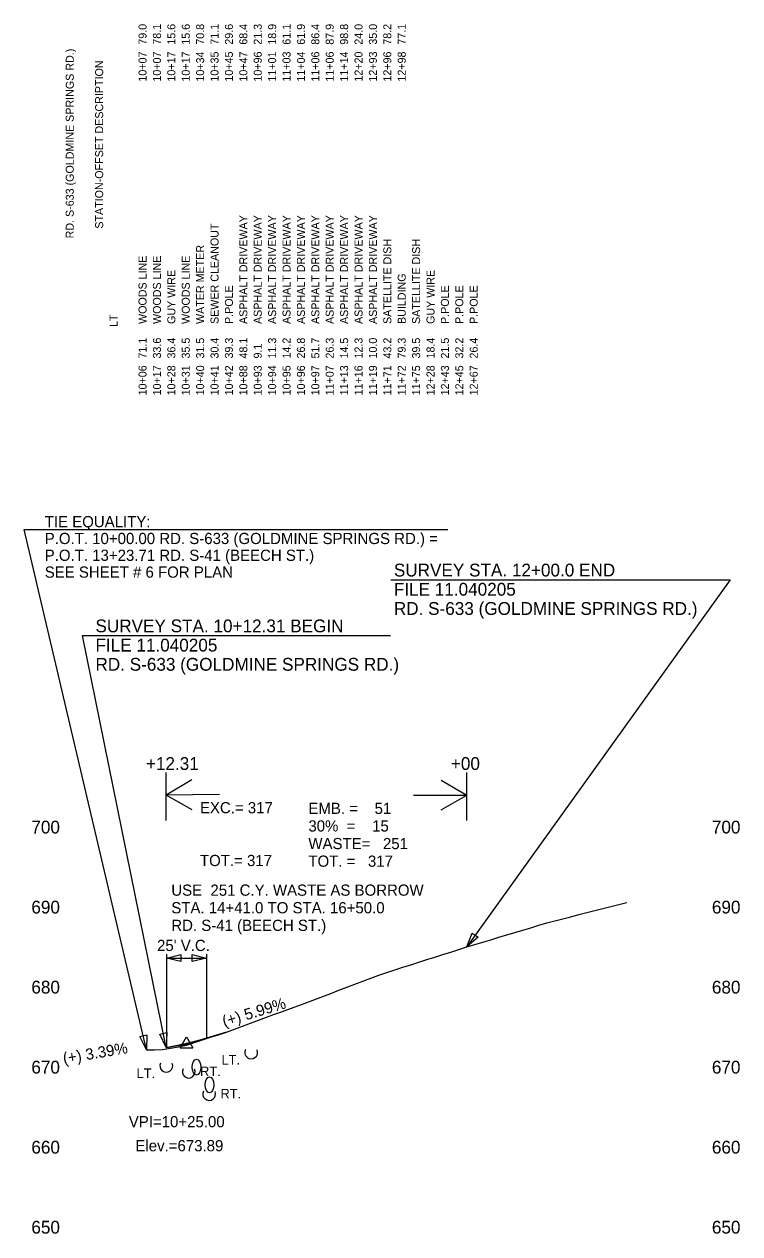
# Model space of a CAD drawing. Extents: x 16382402 to 16388022, y 46194326 to 46202918.
# Drawn here: x 16384675 to 16385122, y 46196922 to 46197677 of the extents above; entities that cross this region are included whole.
import ezdxf

# ---------------------------------------------------------------- set-up
doc = ezdxf.new("R2010")
doc.units = 0
for name, color, linetype in [('Default', 7, 'Continuous'), ('RD_DDB_ElevTX', 7, 'Continuous'), ('RD_DDB_GradeTX', 7, 'Continuous'), ('RD_DDB_Profile_EX', 7, 'Continuous'), ('RD_DDB_Profile_Lbl', 7, 'Continuous'), ('RD_DDB_Profile_PR', 7, 'Continuous'), ('RD_DDB_VCLbl', 7, 'Continuous'), ('RD_HC_Data', 7, 'Continuous'), ('RD_PD_Final_TX', 7, 'Continuous'), ('RD_TX_Bldg', 7, 'Continuous'), ('RD_TX_Drainage', 7, 'Continuous')]:
    doc.layers.add(name, color=color, linetype=linetype)

msp = doc.modelspace()

# ---------------------------------------------------------------- linework, layer by layer
at = {"layer": 'Default'}
for p, q in [((16384763.66, 46197179.88), (16384763.66, 46197209.88)), ((16384951.35, 46197179.88), (16384951.35, 46197209.88)), ((16384779.68, 46197205.24), (16384763.66, 46197195.8)), ((16384935.25, 46197205.1), (16384951.35, 46197195.8)), ((16384796.99, 46197196.09), (16384763.66, 46197195.8)), ((16384779.84, 46197186.64), (16384763.66, 46197195.8)), ((16384918.02, 46197195.8), (16384951.35, 46197195.8)), ((16384935.25, 46197186.5), (16384951.35, 46197195.8))]:
    msp.add_line(p, q, dxfattribs=at)
for centre in [(16384816.72, 46197035.01), (16384763.69, 46197026.63), (16384777.69, 46197022.98), (16384790.44, 46197009.03)]:
    msp.add_arc(centre, 3.98, 153.82804, 22.53319, dxfattribs=at)
at = {"layer": 'RD_DDB_GradeTX'}
for p in [(16384801.35, 46197047.74), (16384763.66, 46197038.1)]:
    msp.add_line(p, (16384776.35, 46197040.25), dxfattribs=at)
at = {"layer": 'RD_DDB_Profile_EX'}
msp.add_lwpolyline([(16384751.35, 46197036.69), (16384756.35, 46197036.73), (16384761.35, 46197036.83), (16384766.35, 46197037.65), (16384771.35, 46197038.48), (16384776.35, 46197039.54), (16384781.35, 46197041.17), (16384786.35, 46197042.81), (16384791.35, 46197044.45), (16384796.35, 46197046.09), (16384801.35, 46197047.74), (16384806.35, 46197049.59), (16384811.35, 46197051.44), (16384816.35, 46197053.29), (16384821.35, 46197055.14), (16384826.35, 46197056.99), (16384831.35, 46197058.84), (16384836.35, 46197060.69), (16384841.35, 46197062.52), (16384846.35, 46197064.36), (16384851.35, 46197066.21), (16384856.35, 46197068.1), (16384861.35, 46197070.02), (16384866.35, 46197071.93), (16384871.35, 46197073.83), (16384876.35, 46197075.71), (16384881.35, 46197077.59), (16384886.35, 46197079.47), (16384891.35, 46197081.35), (16384896.35, 46197083.23), (16384901.35, 46197085.04), (16384906.35, 46197086.62), (16384911.35, 46197088.2), (16384916.35, 46197089.79), (16384921.35, 46197091.37), (16384926.35, 46197092.99), (16384931.35, 46197094.57), (16384936.35, 46197096.16), (16384941.35, 46197097.74), (16384946.35, 46197099.32), (16384951.35, 46197100.94), (16384956.35, 46197102.45), (16384961.35, 46197103.95), (16384966.35, 46197105.45), (16384971.35, 46197106.94), (16384976.35, 46197108.44), (16384981.35, 46197109.94), (16384986.35, 46197111.43), (16384991.35, 46197112.93), (16384996.35, 46197114.43), (16385001.35, 46197115.93), (16385006.35, 46197117.31), (16385011.35, 46197118.57), (16385016.35, 46197119.83), (16385021.35, 46197121.09), (16385026.35, 46197122.34), (16385031.35, 46197123.6), (16385036.35, 46197124.85), (16385041.35, 46197126.11), (16385046.35, 46197127.36), (16385051.35, 46197128.62)], dxfattribs=at)
at = {"layer": 'RD_DDB_Profile_PR'}
for p, q in [((16384788.85, 46197044), (16384801.35, 46197047.74)), ((16384763.66, 46197038.1), (16384763.85, 46197038.13))]:
    msp.add_line(p, q, dxfattribs=at)
msp.add_spline([(16384763.85, 46197038.13), (16384764.35, 46197038.22), (16384764.85, 46197038.3), (16384765.35, 46197038.39), (16384765.85, 46197038.48), (16384766.35, 46197038.57), (16384766.85, 46197038.66), (16384767.35, 46197038.76), (16384767.85, 46197038.85), (16384768.35, 46197038.95), (16384768.85, 46197039.05), (16384769.35, 46197039.14), (16384769.85, 46197039.24), (16384770.35, 46197039.34), (16384770.85, 46197039.45), (16384771.35, 46197039.55), (16384771.85, 46197039.66), (16384772.35, 46197039.76), (16384772.85, 46197039.87), (16384773.35, 46197039.98), (16384773.85, 46197040.09), (16384774.35, 46197040.2), (16384774.85, 46197040.31), (16384775.35, 46197040.43), (16384775.85, 46197040.54), (16384776.35, 46197040.66), (16384776.85, 46197040.78), (16384777.35, 46197040.9), (16384777.85, 46197041.02), (16384778.35, 46197041.14), (16384778.85, 46197041.26), (16384779.35, 46197041.39), (16384779.85, 46197041.51), (16384780.35, 46197041.64), (16384780.85, 46197041.77), (16384781.35, 46197041.9), (16384781.85, 46197042.03), (16384782.35, 46197042.16), (16384782.85, 46197042.29), (16384783.35, 46197042.43), (16384783.85, 46197042.56), (16384784.35, 46197042.7), (16384784.85, 46197042.84), (16384785.35, 46197042.98), (16384785.85, 46197043.12), (16384786.35, 46197043.27), (16384786.85, 46197043.41), (16384787.35, 46197043.55), (16384787.85, 46197043.7), (16384788.35, 46197043.85), (16384788.85, 46197044)], degree=3, dxfattribs=at)
at = {"layer": 'RD_DDB_VCLbl'}
for p, q in [((16384763.85, 46197096.5), (16384763.85, 46197038.13)), ((16384763.85, 46197094), (16384788.85, 46197094)), ((16384788.85, 46197096.5), (16384788.85, 46197044))]:
    msp.add_line(p, q, dxfattribs=at)
at = {"layer": 'RD_HC_Data'}
for p, q in [((16384674.94, 46197361.72), (16384939.6, 46197361.72)), ((16384751.35, 46197036.69), (16384674.94, 46197361.72)), ((16384772.38, 46197037.96), (16384776.35, 46197044.84)), ((16384776.35, 46197044.84), (16384780.32, 46197037.96)), ((16384772.38, 46197037.96), (16384780.32, 46197037.96))]:
    msp.add_line(p, q, dxfattribs=at)
msp.add_circle((16384776.35, 46197040.25), 0.529, dxfattribs=at)
at = {"layer": 'RD_PD_Final_TX'}
for p, q in [((16384904, 46197330.38), (16385115.78, 46197330.38)), ((16385115.78, 46197330.38), (16384951.35, 46197100.94)), ((16384711.44, 46197295.49), (16384903.65, 46197295.49)), ((16384763.66, 46197038.1), (16384711.44, 46197295.49))]:
    msp.add_line(p, q, dxfattribs=at)
at = {"layer": 'RD_TX_Drainage'}
for points in [[(16384958.42, 46197106.95), (16384951.35, 46197100.94), (16384954.76, 46197109.57)], [(16384772.85, 46197091.75), (16384763.85, 46197094), (16384772.85, 46197096.25)], [(16384779.85, 46197096.25), (16384788.85, 46197094), (16384779.85, 46197091.75)], [(16384764.08, 46197047.37), (16384763.66, 46197038.1), (16384759.67, 46197046.47)], [(16384751.48, 46197045.97), (16384751.35, 46197036.69), (16384747.1, 46197044.94)]]:
    msp.add_lwpolyline(points, close=True, dxfattribs=at)
for centre in [(16384782.53, 46197025.8), (16384790.66, 46197014.8)]:
    msp.add_ellipse(centre, major_axis=(0, 5), ratio=0.529493, dxfattribs=at)

# ---------------------------------------------------------------- texts
at = {"layer": 'Default'}
for s, height, p in [('+12.31', 8, (16384750.95, 46197211.51)), ('+00', 8, (16384941.4, 46197211.51)), ('EXC.= 317', 7, (16384784.7, 46197184.44)), ('EMB. =    51', 7, (16384852.42, 46197184.02)), ('30%  =    15', 7, (16384852.42, 46197173.02)), ('WASTE=   251', 7, (16384852.42, 46197162.02)), ('TOT.= 317', 7, (16384784.7, 46197151.44)), ('TOT. =   317', 7, (16384852.42, 46197151.02)), ('USE  251 C.Y. WASTE AS BORROW', 7, (16384766.81, 46197132.92)), ('STA. 14+41.0 TO STA. 16+50.0', 7, (16384766.81, 46197121.92)), ('RD. S-41 (BEECH ST.)', 7, (16384766.81, 46197110.92)), ('LT.', 6, (16384798.13, 46197027.39)), ('LT.', 6, (16384745.1, 46197019.01)), ('RT.', 6, (16384784.77, 46197020.2)), ('RT.', 6, (16384797.52, 46197006.25))]:
    msp.add_text(s, height=height, dxfattribs=at).set_placement(p)
at = {"layer": 'RD_DDB_ElevTX'}
for s, p in [('700', (16384679.41, 46197171.8)), ('700', (16385104.41, 46197171.8)), ('690', (16384679.41, 46197121.8)), ('690', (16385104.41, 46197121.8)), ('680', (16384679.41, 46197071.8)), ('680', (16385104.41, 46197071.8)), ('670', (16384679.41, 46197021.8)), ('670', (16385104.41, 46197021.8)), ('660', (16384679.41, 46196971.8)), ('660', (16385104.41, 46196971.8)), ('650', (16384679.41, 46196921.8)), ('650', (16385104.41, 46196921.8))]:
    msp.add_text(s, height=8, dxfattribs=at).set_placement(p)
at = {"layer": 'RD_DDB_GradeTX'}
for s, rotation, p in [('(+) 5.99%', 16.81672, (16384799.86, 46197050.93)), ('(+) 3.39%', 9.62593, (16384699.74, 46197027.8))]:
    msp.add_text(s, height=7, rotation=rotation, dxfattribs=at).set_placement(p)
at = {"layer": 'RD_DDB_Profile_Lbl'}
for s, p in [('VPI=10+25.00', (16384740.26, 46196988.25)), ('Elev.=673.89', (16384744.4, 46196973.25))]:
    msp.add_text(s, height=7, dxfattribs=at).set_placement(p)
at = {"layer": 'RD_DDB_VCLbl'}
msp.add_text("25' V.C.", height=7, dxfattribs=at).set_placement((16384757.91, 46197098.37))
at = {"layer": 'RD_HC_Data'}
for s, p in [('TIE EQUALITY:', (16384687.76, 46197363.14)), ('P.O.T. 10+00.00 RD. S-633 (GOLDMINE SPRINGS RD.) =', (16384687.76, 46197352.64)), ('P.O.T. 13+23.71 RD. S-41 (BEECH ST.)', (16384687.76, 46197342.14)), ('SEE SHEET # 6 FOR PLAN', (16384687.76, 46197331.64))]:
    msp.add_text(s, height=7, dxfattribs=at).set_placement(p)
at = {"layer": 'RD_PD_Final_TX'}
for s, p in [('SURVEY STA. 12+00.0 END', (16384905.8, 46197332.39)), ('FILE 11.040205', (16384905.8, 46197320.39)), ('RD. S-633 (GOLDMINE SPRINGS RD.)', (16384905.8, 46197308.39)), ('SURVEY STA. 10+12.31 BEGIN', (16384719.44, 46197297.51)), ('FILE 11.040205', (16384719.44, 46197285.51)), ('RD. S-633 (GOLDMINE SPRINGS RD.)', (16384719.44, 46197273.51))]:
    msp.add_text(s, height=8, dxfattribs=at).set_placement(p)
at = {"layer": 'RD_TX_Bldg'}
for s, p in [('79.0', (16384751.35, 46197664.65)), ('78.1', (16384760.34, 46197664.65)), ('15.6', (16384769.33, 46197664.65)), ('15.6', (16384778.33, 46197664.65)), ('70.8', (16384787.32, 46197664.65)), ('71.1', (16384796.31, 46197664.65)), ('29.6', (16384805.3, 46197664.65)), ('68.4', (16384814.29, 46197664.65)), ('21.3', (16384823.28, 46197664.65)), ('18.9', (16384832.28, 46197664.65)), ('61.1', (16384841.27, 46197664.65)), ('61.9', (16384850.26, 46197664.65)), ('86.4', (16384859.25, 46197664.65)), ('87.9', (16384868.24, 46197664.65)), ('98.8', (16384877.23, 46197664.65)), ('24.0', (16384886.23, 46197664.65)), ('35.0', (16384895.22, 46197664.65)), ('78.2', (16384904.21, 46197664.65)), ('77.1', (16384913.2, 46197664.65)), ('RD. S-633 (GOLDMINE SPRINGS RD.)', (16384705.89, 46197543.64)), ('10+07', (16384751.35, 46197641.6)), ('10+07', (16384760.34, 46197641.6)), ('10+17', (16384769.33, 46197641.6)), ('10+17', (16384778.33, 46197641.6)), ('10+34', (16384787.32, 46197641.6)), ('10+35', (16384796.31, 46197641.6)), ('10+45', (16384805.3, 46197641.6)), ('10+47', (16384814.29, 46197641.6)), ('10+96', (16384823.28, 46197641.6)), ('11+01', (16384832.28, 46197641.6)), ('11+03', (16384841.27, 46197641.6)), ('11+04', (16384850.26, 46197641.6)), ('11+06', (16384859.25, 46197641.6)), ('11+06', (16384868.24, 46197641.6)), ('11+14', (16384877.23, 46197641.6)), ('12+20', (16384886.23, 46197641.6)), ('12+93', (16384895.22, 46197641.6)), ('12+96', (16384904.21, 46197641.6)), ('12+98', (16384913.2, 46197641.6)), ('STATION-OFFSET DESCRIPTION', (16384724.25, 46197549.7)), ('ASPHALT DRIVEWAY', (16384814.29, 46197490.16)), ('ASPHALT DRIVEWAY', (16384823.28, 46197490.16)), ('ASPHALT DRIVEWAY', (16384832.28, 46197490.16)), ('ASPHALT DRIVEWAY', (16384841.27, 46197490.16)), ('ASPHALT DRIVEWAY', (16384850.26, 46197490.16)), ('ASPHALT DRIVEWAY', (16384859.25, 46197490.16)), ('ASPHALT DRIVEWAY', (16384868.24, 46197490.16)), ('ASPHALT DRIVEWAY', (16384877.23, 46197490.16)), ('ASPHALT DRIVEWAY', (16384886.23, 46197490.16)), ('ASPHALT DRIVEWAY', (16384895.22, 46197490.16)), ('SEWER CLEANOUT', (16384796.31, 46197490.16)), ('WATER METER', (16384787.32, 46197490.16)), ('SATELLITE DISH', (16384904.21, 46197490.16)), ('SATELLITE DISH', (16384922.19, 46197490.16)), ('WOODS LINE', (16384751.35, 46197490.16)), ('WOODS LINE', (16384760.34, 46197490.16)), ('WOODS LINE', (16384778.33, 46197490.16)), ('GUY WIRE', (16384769.33, 46197490.16)), ('GUY WIRE', (16384931.19, 46197490.16)), ('BUILDING', (16384913.2, 46197490.16)), ('P.POLE', (16384805.3, 46197490.16)), ('P.POLE', (16384940.18, 46197490.16)), ('P.POLE', (16384949.17, 46197490.16)), ('P.POLE', (16384958.16, 46197490.16)), ('LT', (16384733.24, 46197488.25)), ('71.1', (16384751.35, 46197468.58)), ('33.6', (16384760.34, 46197468.58)), ('36.4', (16384769.33, 46197468.58)), ('35.5', (16384778.33, 46197468.58)), ('31.5', (16384787.32, 46197468.58)), ('30.4', (16384796.31, 46197468.58)), ('39.3', (16384805.3, 46197468.58)), ('48.1', (16384814.29, 46197468.58)), ('9.1', (16384823.28, 46197468.58)), ('11.3', (16384832.28, 46197468.58)), ('14.2', (16384841.27, 46197468.58)), ('26.8', (16384850.26, 46197468.58)), ('51.7', (16384859.25, 46197468.58)), ('26.3', (16384868.24, 46197468.58)), ('14.5', (16384877.23, 46197468.58)), ('12.3', (16384886.23, 46197468.58)), ('10.0', (16384895.22, 46197468.58)), ('43.2', (16384904.21, 46197468.58)), ('79.3', (16384913.2, 46197468.58)), ('39.5', (16384922.19, 46197468.58)), ('18.4', (16384931.19, 46197468.58)), ('21.5', (16384940.18, 46197468.58)), ('32.2', (16384949.17, 46197468.58)), ('26.4', (16384958.16, 46197468.58)), ('10+06', (16384751.35, 46197445.53)), ('10+17', (16384760.34, 46197445.53)), ('10+28', (16384769.33, 46197445.53)), ('10+31', (16384778.33, 46197445.53)), ('10+40', (16384787.32, 46197445.53)), ('10+41', (16384796.31, 46197445.53)), ('10+42', (16384805.3, 46197445.53)), ('10+88', (16384814.29, 46197445.53)), ('10+93', (16384823.28, 46197445.53)), ('10+94', (16384832.28, 46197445.53)), ('10+95', (16384841.27, 46197445.53)), ('10+96', (16384850.26, 46197445.53)), ('10+97', (16384859.25, 46197445.53)), ('11+07', (16384868.24, 46197445.53)), ('11+13', (16384877.23, 46197445.53)), ('11+16', (16384886.23, 46197445.53)), ('11+19', (16384895.22, 46197445.53)), ('11+71', (16384904.21, 46197445.53)), ('11+72', (16384913.2, 46197445.53)), ('11+75', (16384922.19, 46197445.53)), ('12+28', (16384931.19, 46197445.53)), ('12+43', (16384940.18, 46197445.53)), ('12+45', (16384949.17, 46197445.53)), ('12+67', (16384958.16, 46197445.53))]:
    msp.add_text(s, height=5, rotation=90, dxfattribs=at).set_placement(p)

doc.saveas('drawing.dxf')
